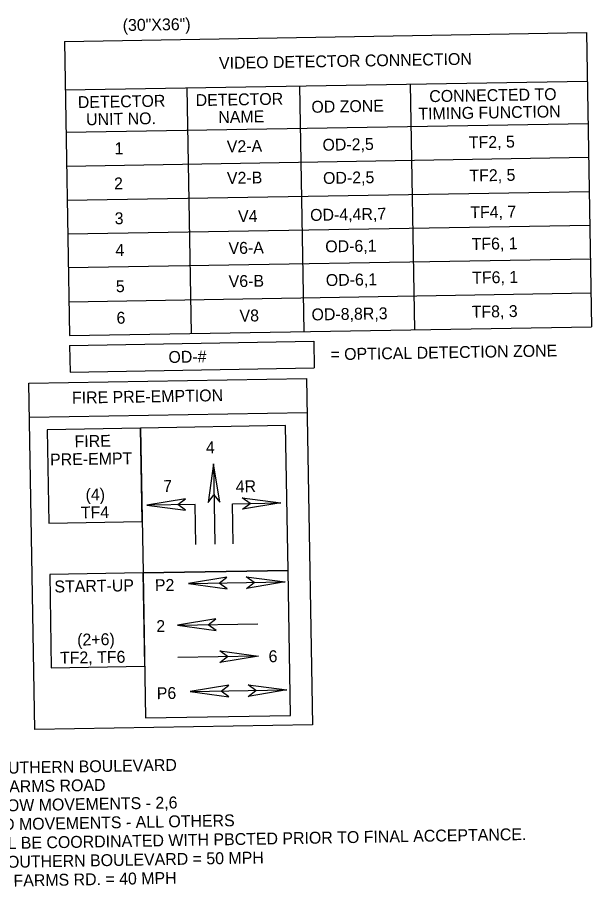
# Model space of a CAD drawing. Extents: x 924596 to 926137, y 853397 to 853834.
# Drawn here: x 925469.4 to 925604.5, y 853400.9 to 853606.4 of the extents above; entities that cross this region are included whole.
import ezdxf

# ---------------------------------------------------------------- set-up
doc = ezdxf.new("R2010")
doc.units = 0
for name, color, linetype in [('SignalSOP', 7, 'Continuous'), ('SumBoxBorder_dp', 7, 'Continuous'), ('SumBoxLines_dp', 7, 'Continuous'), ('TextLabel', 7, 'Continuous'), ('TextMisc', 7, 'Continuous'), ('TextTables', 7, 'Continuous')]:
    doc.layers.add(name, color=color, linetype=linetype)

msp = doc.modelspace()

# ---------------------------------------------------------------- linework, layer by layer
at = {"layer": 'SignalSOP'}
for p, q in [((925472.25, 853512.32), (925537.58, 853513.43)), ((925498.41, 853509.74), (925476.44, 853509.37)), ((925476.44, 853509.37), (925476.81, 853487.39)), ((925532.52, 853510.32), (925498.41, 853509.74)), ((925498.41, 853509.74), (925498.99, 853475.63)), ((925498.79, 853487.77), (925498.41, 853509.74)), ((925533.1, 853476.21), (925532.52, 853510.32)), ((925515.53, 853501.34), (925514.33, 853492.22)), ((925515.53, 853501.34), (925515.86, 853482.39)), ((925517.05, 853492.27), (925515.53, 853501.34)), ((925508.97, 853493.12), (925499.9, 853491.6)), ((925507.17, 853491.72), (925508.97, 853493.12)), ((925514.33, 853492.22), (925515.66, 853494.06)), ((925515.66, 853494.06), (925517.05, 853492.27)), ((925520.06, 853491.94), (925531.43, 853492.13)), ((925524.16, 853492.01), (925522.31, 853493.34)), ((925522.31, 853493.34), (925531.43, 853492.13)), ((925531.43, 853492.13), (925522.36, 853490.62)), ((925511.26, 853491.79), (925499.9, 853491.6)), ((925499.9, 853491.6), (925509.01, 853490.39)), ((925509.01, 853490.39), (925507.17, 853491.72)), ((925511.43, 853482.32), (925511.26, 853491.79)), ((925520.23, 853482.47), (925520.06, 853491.94)), ((925522.36, 853490.62), (925524.16, 853492.01)), ((925476.81, 853487.39), (925498.79, 853487.77)), ((925498.99, 853475.63), (925477.02, 853475.26)), ((925533.1, 853476.21), (925498.99, 853475.63)), ((925498.99, 853475.63), (925533.1, 853476.21)), ((925498.99, 853475.63), (925499.57, 853441.53)), ((925499.37, 853453.66), (925498.99, 853475.63)), ((925533.68, 853442.11), (925533.1, 853476.21)), ((925477.02, 853475.26), (925477.39, 853453.29)), ((925518.73, 853474.65), (925509.66, 853473.13)), ((925516.94, 853473.25), (925518.73, 853474.65)), ((925525.12, 853473.39), (925523.28, 853474.73)), ((925523.28, 853474.73), (925532.4, 853473.52)), ((925509.66, 853473.13), (925532.4, 853473.52)), ((925509.66, 853473.13), (925518.78, 853471.92)), ((925518.78, 853471.92), (925516.94, 853473.25)), ((925532.4, 853473.52), (925523.33, 853472)), ((925523.33, 853472), (925525.12, 853473.39)), ((925516.13, 853464.85), (925507.06, 853463.33)), ((925507.06, 853463.33), (925526.01, 853463.65)), ((925507.06, 853463.33), (925516.18, 853462.12)), ((925514.34, 853463.45), (925516.13, 853464.85)), ((925516.18, 853462.12), (925514.34, 853463.45)), ((925518.86, 853455.95), (925517.02, 853457.28)), ((925517.02, 853457.28), (925526.14, 853456.07)), ((925526.14, 853456.07), (925507.19, 853455.75)), ((925526.14, 853456.07), (925517.07, 853454.55)), ((925517.07, 853454.55), (925518.86, 853455.95)), ((925477.39, 853453.29), (925499.37, 853453.66)), ((925519.16, 853449.21), (925510.09, 853447.69)), ((925517.37, 853447.81), (925519.16, 853449.21)), ((925525.55, 853447.95), (925523.71, 853449.29)), ((925523.71, 853449.29), (925532.83, 853448.08)), ((925510.09, 853447.69), (925532.83, 853448.08)), ((925510.09, 853447.69), (925519.21, 853446.48)), ((925519.21, 853446.48), (925517.37, 853447.81)), ((925532.83, 853448.08), (925523.76, 853446.56)), ((925523.76, 853446.56), (925525.55, 853447.95)), ((925499.57, 853441.53), (925533.68, 853442.11))]:
    msp.add_line(p, q, dxfattribs=at)
msp.add_lwpolyline([(925472.11, 853520.3), (925537.45, 853521.42), (925538.83, 853439.87), (925473.5, 853438.76)], close=True, dxfattribs=at)
at = {"layer": 'SumBoxBorder_dp'}
for p, q in [((925480.49, 853600.77), (925603.35, 853602.86)), ((925603.35, 853602.86), (925604.53, 853533.61)), ((925480.49, 853600.77), (925481.67, 853531.52)), ((925480.69, 853589.38), (925603.54, 853591.46)), ((925480.86, 853579.4), (925603.71, 853581.49)), ((925481.67, 853531.52), (925604.53, 853533.61)), ((925481.71, 853529.22), (925539.18, 853530.2)), ((925481.71, 853529.22), (925481.82, 853522.92)), ((925539.18, 853530.2), (925539.29, 853523.9)), ((925481.82, 853522.92), (925539.29, 853523.9))]:
    msp.add_line(p, q, dxfattribs=at)
at = {"layer": 'SumBoxLines_dp'}
for p, q in [((925561.85, 853590.76), (925562.84, 853532.9)), ((925509.31, 853589.86), (925510.29, 853532.01)), ((925535.82, 853590.31), (925536.8, 853532.46)), ((925480.99, 853571.42), (925603.85, 853573.51)), ((925481.13, 853563.39), (925603.99, 853565.48)), ((925481.26, 853555.46), (925604.12, 853557.55)), ((925481.4, 853547.54), (925604.26, 853549.63)), ((925481.54, 853539.5), (925604.39, 853541.59))]:
    msp.add_line(p, q, dxfattribs=at)

# ---------------------------------------------------------------- texts
at = {"layer": 'SignalSOP'}
for s, p in [('FIRE PRE-EMPTION', (925482.28, 853515.49)), ('FIRE', (925482.89, 853505.22)), ('4', (925513.81, 853503.8)), ('PRE-EMPT', (925477.13, 853500.93)), ('7', (925503.74, 853494.67)), ('4R', (925520.82, 853494.59)), ('(4)', (925485.48, 853492.67)), ('TF4', (925484.37, 853488.45)), ('START-UP', (925478.15, 853471.03)), ('P2', (925501.8, 853471.35)), ('2', (925502.13, 853461.71)), ('(2+6)', (925483.51, 853458.52)), ('TF2, TF6', (925479.46, 853454.25)), ('6', (925528.55, 853454.61)), ('P6', (925502.24, 853445.91))]:
    msp.add_text(s, height=2.8, rotation=0.9741, dxfattribs=at).set_placement(p)
at = {"layer": 'TextLabel'}
for s, p in [('VIDEO DETECTOR CONNECTION', (925516.89, 853594.29)), ('DETECTOR', (925511.39, 853585.55)), ('CONNECTED TO', (925566.37, 853586.48)), ('DETECTOR', (925483.66, 853585.08)), ('OD ZONE', (925538.63, 853583.97)), ('TIMING FUNCTION', (925563.8, 853582.36)), ('UNIT NO.', (925485.61, 853581.03)), ('NAME', (925516.72, 853581.56)), ('TF2, 5', (925575.68, 853575.62)), ('1', (925492.3, 853574.2)), ('V2-A', (925518.72, 853574.65)), ('OD-2,5', (925541.24, 853575.03)), ('OD-2,5', (925541.37, 853567.21)), ('TF2, 5', (925575.81, 853567.79)), ('2', (925492.19, 853565.93)), ('V2-B', (925518.75, 853567.22)), ('TF4, 7', (925576.01, 853559.15)), ('3', (925492.33, 853557.72)), ('V4', (925521.37, 853558.22)), ('OD-4,4R,7', (925538.33, 853558.51)), ('OD-6,1', (925541.89, 853551.1)), ('TF6, 1', (925576.33, 853551.69)), ('4', (925492.51, 853550.26)), ('V6-A', (925519.12, 853550.71)), ('V6-B', (925519.16, 853542.9)), ('OD-6,1', (925542.02, 853543.17)), ('TF6, 1', (925576.46, 853543.76)), ('5', (925492.61, 853541.73)), ('V8', (925521.72, 853534.8)), ('OD-8,8R,3', (925538.66, 853535.08)), ('TF8, 3', (925576.34, 853535.72)), ('6', (925492.76, 853534.3)), (' = OPTICAL DETECTION ZONE', (925542.07, 853525.7)), ('OD-#', (925504.99, 853525.07))]:
    msp.add_text(s, height=2.8, rotation=0.9741, dxfattribs=at).set_placement(p)
at = {"layer": 'TextMisc'}
for s, p in [('MAJOR STREET IS SR 80 / SOUTHERN BOULEVARD', (925413.77, 853427.45)), ('MINOR STREET IS BENOIST FARMS ROAD', (925413.84, 853423.02)), ('FLASHING OPERATION: YELLOW MOVEMENTS - 2,6', (925413.92, 853418.59)), ('  RED MOVEMENTS - ALL OTHERS', (925458.79, 853414.93)), ('CONTROLLER TIMINGS SHALL BE COORDINATED WITH PBCTED PRIOR TO FINAL ACCEPTANCE.', (925414.07, 853409.72)), ('POSTED SPEED ON SR 80 / SOUTHERN BOULEVARD = 50 MPH', (925414.15, 853405.29)), ('POSTED SPEED ON BENOIST FARMS RD. = 40 MPH', (925414.23, 853400.86))]:
    msp.add_text(s, height=2.8, rotation=0.9944, dxfattribs=at).set_placement(p)
at = {"layer": 'TextTables'}
msp.add_text('(30"X36")', height=2.8, rotation=0.9741, dxfattribs=at).set_placement((925494.22, 853603.22))

doc.saveas('drawing.dxf')
